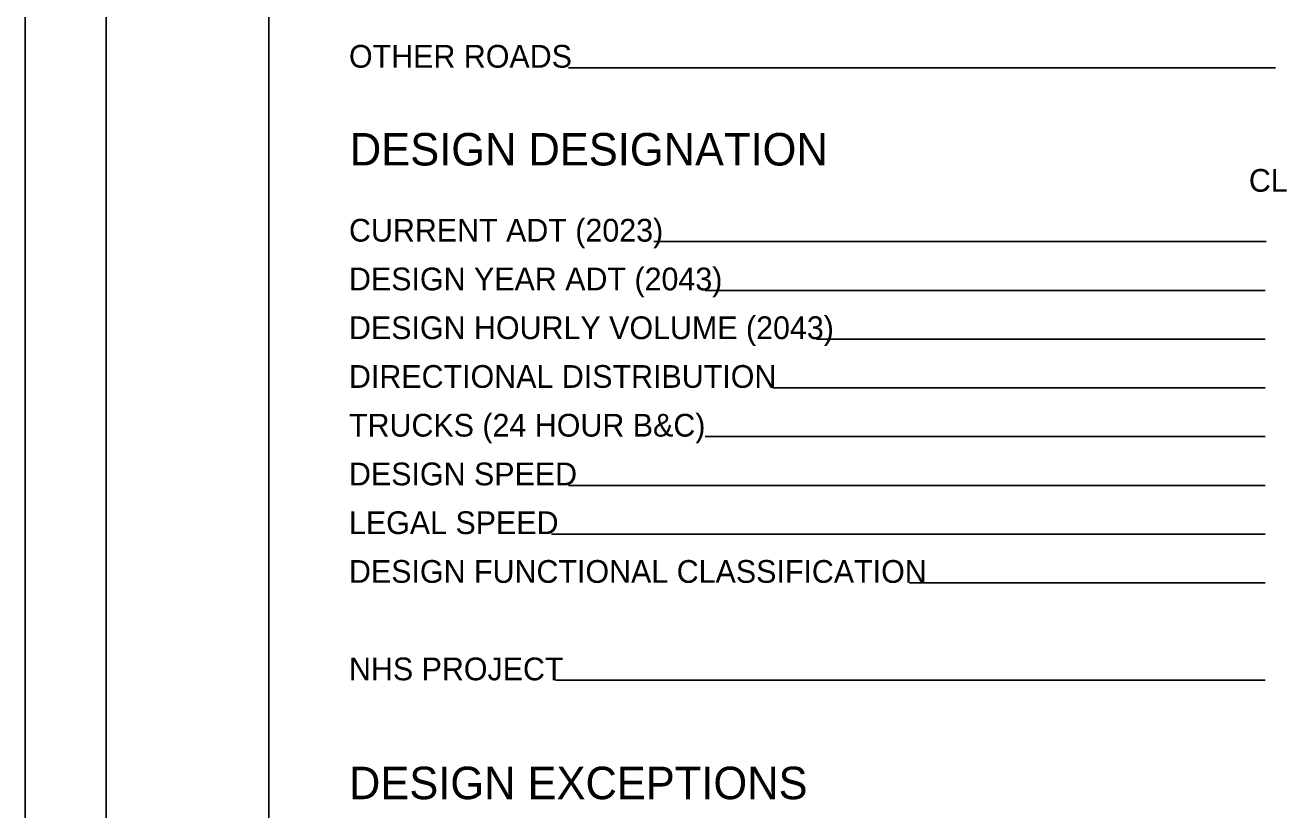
# Model space of a CAD drawing. Extents: x 0 to 34, y 0 to 22.
# Drawn here: x 0 to 7.72, y 6.31 to 11.14 of the extents above; entities that cross this region are included whole.
import ezdxf

# ---------------------------------------------------------------- set-up
doc = ezdxf.new("R2010")
doc.units = 0
for name, color, linetype in [('SH_Border', 7, 'Continuous'), ('SH_Cut_Line', 7, 'Continuous'), ('SH_Data', 7, 'Continuous'), ('SH_Text', 7, 'Continuous')]:
    doc.layers.add(name, color=color, linetype=linetype)

msp = doc.modelspace()

# ---------------------------------------------------------------- linework, layer by layer
at = {"layer": 'SH_Border'}
for points in [[(0.5, 21.5), (1.5, 21.5), (1.5, 0.5), (0.5, 0.5)], [(1.5, 21.5), (33.5, 21.5), (33.5, 0.5), (1.5, 0.5)]]:
    msp.add_lwpolyline(points, close=True, dxfattribs=at)
at = {"layer": 'SH_Cut_Line'}
msp.add_lwpolyline([(0, 0), (34, 0), (34, 22), (0, 22)], close=True, dxfattribs=at)
at = {"layer": 'SH_Data'}
for p, q in [((7.7, 10.8767), (3.3471, 10.8767)), ((7.6424, 9.8062), (3.871, 9.8062)), ((7.6368, 9.5062), (4.1885, 9.5062)), ((7.6368, 9.2062), (4.8723, 9.2062)), ((7.6368, 8.9062), (4.6037, 8.9062)), ((7.6368, 8.6062), (4.1885, 8.6062)), ((7.6368, 8.3062), (3.346, 8.3062)), ((7.6368, 8.0062), (3.2422, 8.0062)), ((7.6368, 7.7062), (5.445, 7.7062)), ((7.6368, 7.1062), (3.2669, 7.1062))]:
    msp.add_line(p, q, dxfattribs=at)

# ---------------------------------------------------------------- texts
for s, height, p in [('DESIGN DESIGNATION', 0.2, (2, 10.2747)), ('CLAGUE RD.', 0.14, (7.5355, 10.1131))]:
    msp.add_text(s, height=height, dxfattribs=at).set_placement(p)
at = {"layer": 'SH_Text'}
for s, height, p in [('OTHER ROADS', 0.14, (1.9944, 10.8767)), ('CURRENT ADT (2023)', 0.14, (1.9944, 9.8062)), ('DESIGN YEAR ADT (2043)', 0.14, (1.9944, 9.5062)), ('DESIGN HOURLY VOLUME (2043)', 0.14, (1.9944, 9.2062)), ('DIRECTIONAL DISTRIBUTION', 0.14, (1.9944, 8.9062)), ('TRUCKS (24 HOUR B&C)', 0.14, (1.9944, 8.6062)), ('DESIGN SPEED', 0.14, (1.9944, 8.3062)), ('LEGAL SPEED', 0.14, (1.9944, 8.0062)), ('DESIGN FUNCTIONAL CLASSIFICATION', 0.14, (1.9944, 7.7062)), ('NHS PROJECT', 0.14, (1.9944, 7.1062)), ('DESIGN EXCEPTIONS', 0.2, (1.9944, 6.3744))]:
    msp.add_text(s, height=height, dxfattribs=at).set_placement(p)

doc.saveas('drawing.dxf')
